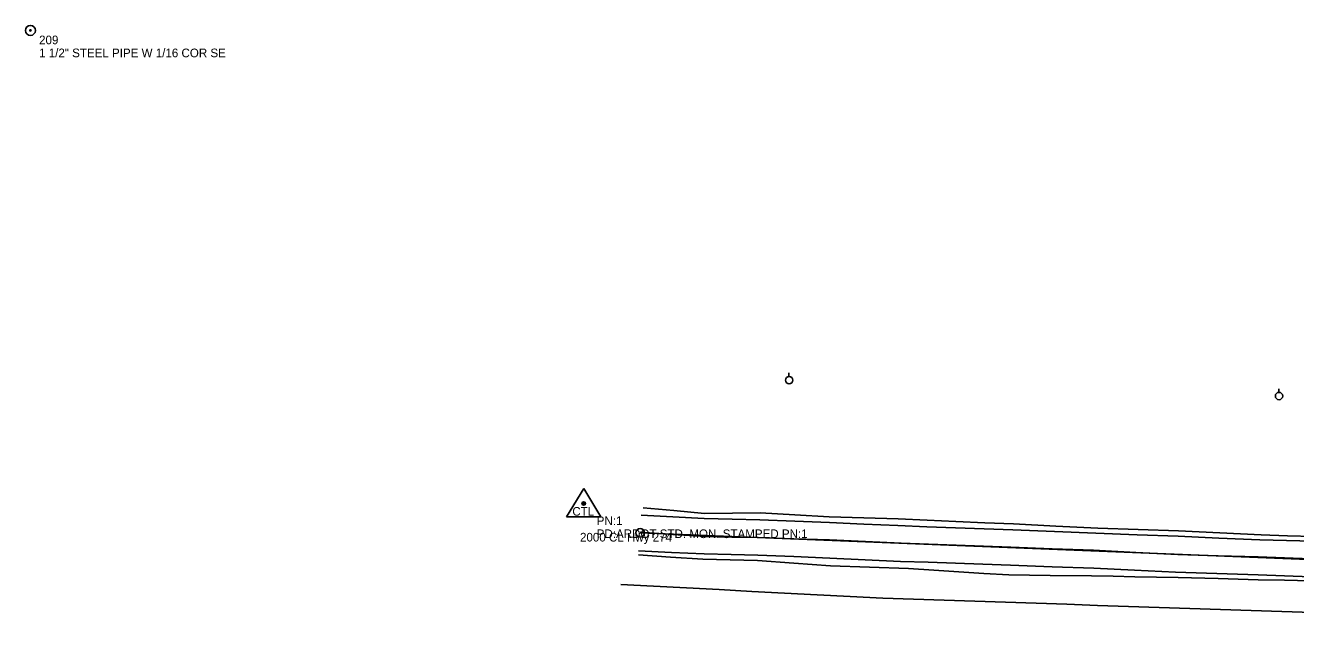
# Model space of a CAD drawing. Extents: x 1138803 to 1169983, y 1655906 to 1658226.
# Drawn here: x 1140126 to 1140860, y 1657617 to 1657972 of the extents above; entities that cross this region are included whole.
import ezdxf

# ---------------------------------------------------------------- set-up
doc = ezdxf.new("R2010")
doc.units = 0
for name, color, linetype in [('S_EDGE_PAVEMENT', 7, 'Continuous'), ('S_EXISTING_ALIGNMENT', 7, 'Continuous'), ('S_EXISTING_ALIGNMENT_ANNOT', 7, 'Continuous'), ('S_IRON_PIN', 7, 'Continuous'), ('S_IRON_PIN_ANNOT', 7, 'Continuous'), ('S_PAVEMENT_CROWN', 7, 'Continuous'), ('S_PRIMARY_CTL', 7, 'Continuous'), ('S_PRIMARY_CTL_ANNOT', 7, 'Continuous'), ('S_SHOULDER', 7, 'Continuous'), ('S_TREE', 7, 'Continuous'), ('S_UTILITY_POLE', 7, 'Continuous')]:
    doc.layers.add(name, color=color, linetype=linetype)

msp = doc.modelspace()

# ---------------------------------------------------------------- linework, layer by layer
at = {"layer": 'S_EDGE_PAVEMENT'}
for points in [[(1140870.32, 1657674.37), (1140854.89, 1657674.78), (1140839.46, 1657675.2), (1140815.87, 1657676.17), (1140792.29, 1657677.15), (1140768.57, 1657678.09), (1140744.85, 1657679.03), (1140720.8, 1657679.93), (1140696.75, 1657680.83), (1140680.17, 1657681.45), (1140663.59, 1657682.08), (1140647.02, 1657682.71), (1140630.44, 1657683.33), (1140610.64, 1657684.19), (1140590.83, 1657685.05), (1140570.76, 1657685.91), (1140550.7, 1657686.77), (1140534.56, 1657687.12), (1140518.43, 1657687.47), (1140500.26, 1657688.37), (1140482.09, 1657689.28)], [(1140868.91, 1657653.76), (1140853.71, 1657654.29), (1140838.5, 1657654.83), (1140814.64, 1657655.67), (1140790.79, 1657656.52), (1140767.18, 1657657.62), (1140743.56, 1657658.72), (1140719.5, 1657659.56), (1140695.43, 1657660.39), (1140679.56, 1657660.97), (1140663.68, 1657661.54), (1140647.81, 1657662.12), (1140631.93, 1657662.69), (1140611.51, 1657663.61), (1140591.09, 1657664.53), (1140570.31, 1657665.4), (1140549.52, 1657666.27), (1140534.01, 1657666.66), (1140518.5, 1657667.05), (1140499.55, 1657667.88), (1140480.6, 1657668.71)]]:
    msp.add_lwpolyline(points, dxfattribs=at)
at = {"layer": 'S_EXISTING_ALIGNMENT'}
msp.add_line((1140481.53, 1657679.14), (1142022.15, 1657617.46), dxfattribs=at)
msp.add_circle((1140481.53, 1657679.14), 2.5, dxfattribs=at)
at = {"layer": 'S_IRON_PIN'}
for radius in [2.91, 0.411, 0.262, 0.212, 0.145, 0.0822, 0.0581]:
    msp.add_circle((1140129.17, 1657969.52), radius, dxfattribs=at)
at = {"layer": 'S_PAVEMENT_CROWN'}
msp.add_lwpolyline([(1140869, 1657664.22), (1140853.76, 1657664.73), (1140838.52, 1657665.24), (1140815.35, 1657665.93), (1140792.18, 1657666.62), (1140767.84, 1657667.86), (1140743.5, 1657669.1), (1140719.59, 1657669.96), (1140695.67, 1657670.82), (1140679.83, 1657671.41), (1140663.99, 1657672), (1140648.15, 1657672.58), (1140632.31, 1657673.17), (1140611.61, 1657674.16), (1140590.92, 1657675.16), (1140570.29, 1657675.77), (1140549.67, 1657676.39), (1140534.42, 1657676.7), (1140519.16, 1657677.01), (1140500.35, 1657678.29), (1140481.54, 1657679.56)], dxfattribs=at)
at = {"layer": 'S_PRIMARY_CTL'}
for p, q in [((1140448.87, 1657704.84), (1140438.83, 1657688.32)), ((1140448.87, 1657704.84), (1140458.69, 1657688.32)), ((1140438.83, 1657688.32), (1140458.69, 1657688.32))]:
    msp.add_line(p, q, dxfattribs=at)
for radius in [1.04, 0.609, 0.344]:
    msp.add_circle((1140448.87, 1657696.13), radius, dxfattribs=at)
at = {"layer": 'S_SHOULDER'}
for points in [[(1140870.68, 1657676.98), (1140855.47, 1657677.47), (1140840.27, 1657677.96), (1140816.35, 1657679.1), (1140792.44, 1657680.24), (1140769.14, 1657681.09), (1140745.84, 1657681.93), (1140721.56, 1657683.11), (1140697.27, 1657684.29), (1140680.61, 1657685.03), (1140663.95, 1657685.78), (1140647.29, 1657686.52), (1140630.63, 1657687.27), (1140610.64, 1657687.83), (1140590.64, 1657688.39), (1140570.75, 1657689.55), (1140550.86, 1657690.72), (1140534.75, 1657690.55), (1140518.64, 1657690.39), (1140500.9, 1657692.01), (1140483.16, 1657693.62)], [(1140868.85, 1657651.41), (1140853.71, 1657651.75), (1140838.57, 1657652.08), (1140815.46, 1657652.68), (1140792.36, 1657653.29), (1140779.81, 1657653.54), (1140767.26, 1657653.79), (1140754.71, 1657654.04), (1140742.16, 1657654.29), (1140718.34, 1657654.55), (1140694.52, 1657654.8), (1140680.04, 1657655.75), (1140665.56, 1657656.71), (1140651.08, 1657657.67), (1140636.6, 1657658.62), (1140613.98, 1657659.4), (1140591.37, 1657660.17), (1140570.29, 1657661.63), (1140549.21, 1657663.1), (1140533.43, 1657663.47), (1140517.65, 1657663.85), (1140499.07, 1657665.16), (1140480.49, 1657666.47)]]:
    msp.add_lwpolyline(points, dxfattribs=at)
at = {"layer": 'S_TREE'}
msp.add_lwpolyline([(1140470.32, 1657649.33), (1140489.24, 1657648.34), (1140508.16, 1657647.34), (1140527.08, 1657646.35), (1140545.99, 1657645.35), (1140564.91, 1657644.36), (1140583.83, 1657643.37), (1140602.74, 1657642.37), (1140621.66, 1657641.38), (1140639.4, 1657640.79), (1140657.13, 1657640.2), (1140674.87, 1657639.62), (1140692.6, 1657639.03), (1140710.34, 1657638.44), (1140728.07, 1657637.85), (1140745.81, 1657637.26), (1140763.54, 1657636.68), (1140781.28, 1657636.09), (1140799.01, 1657635.5), (1140816.75, 1657634.91), (1140834.48, 1657634.33), (1140852.21, 1657633.74), (1140869.95, 1657633.15)], dxfattribs=at)
at = {"layer": 'S_UTILITY_POLE'}
for p, q in [((1140567.42, 1657769.5), (1140567.42, 1657771.61)), ((1140850.49, 1657760.35), (1140850.49, 1657762.46))]:
    msp.add_line(p, q, dxfattribs=at)
for centre in [(1140567.55, 1657767.36), (1140850.61, 1657758.21)]:
    msp.add_circle(centre, 2.13, dxfattribs=at)

# ---------------------------------------------------------------- texts
at = {"layer": 'S_EXISTING_ALIGNMENT_ANNOT'}
msp.add_text('2000 CL Hwy 274', height=5, dxfattribs=at).set_placement((1140446.71, 1657674.14))
at = {"layer": 'S_IRON_PIN_ANNOT'}
for s, p in [('209', (1140134.17, 1657961.52)), ('1 1/2" STEEL PIPE W 1/16 COR SE', (1140134.17, 1657954.02))]:
    msp.add_text(s, height=5, dxfattribs=at).set_placement(p)
at = {"layer": 'S_PRIMARY_CTL'}
msp.add_text('CTL', height=5, rotation=360, dxfattribs=at).set_placement((1140442.28, 1657689.06))
at = {"layer": 'S_PRIMARY_CTL_ANNOT'}
for s, p in [('PN:1', (1140456.37, 1657683.63)), ('PD:ARDOT STD. MON. STAMPED PN:1', (1140456.37, 1657676.13))]:
    msp.add_text(s, height=5, dxfattribs=at).set_placement(p)

doc.saveas('drawing.dxf')
